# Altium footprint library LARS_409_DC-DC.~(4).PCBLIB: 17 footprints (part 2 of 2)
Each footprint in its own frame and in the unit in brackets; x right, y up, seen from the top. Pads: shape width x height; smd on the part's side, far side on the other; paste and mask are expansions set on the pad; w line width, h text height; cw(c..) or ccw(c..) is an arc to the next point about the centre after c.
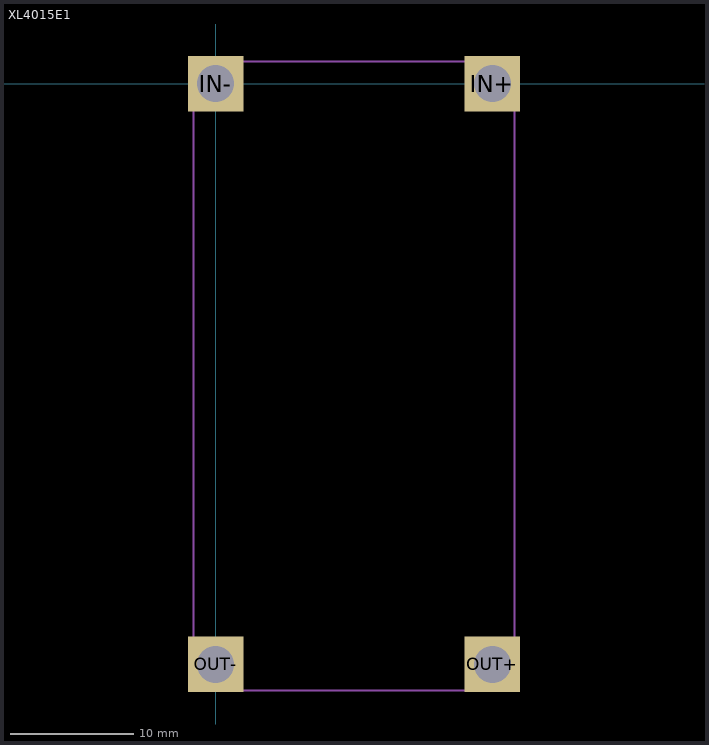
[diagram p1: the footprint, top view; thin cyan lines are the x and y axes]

## XL4015E1 [mm]
pads (4):
  rect 4.5x4.5 / inner round 4.157 / far side rect 4.5x4.5 hole 3: IN+(22.4,0) IN-(0,0) OUT+(22.4,-47) OUT-(0,-47)
tPlace:
  lines w0.152: -1.8,-49.1 24.2,-49.1 24.2,1.8 -1.8,1.8 -1.8,-49.1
